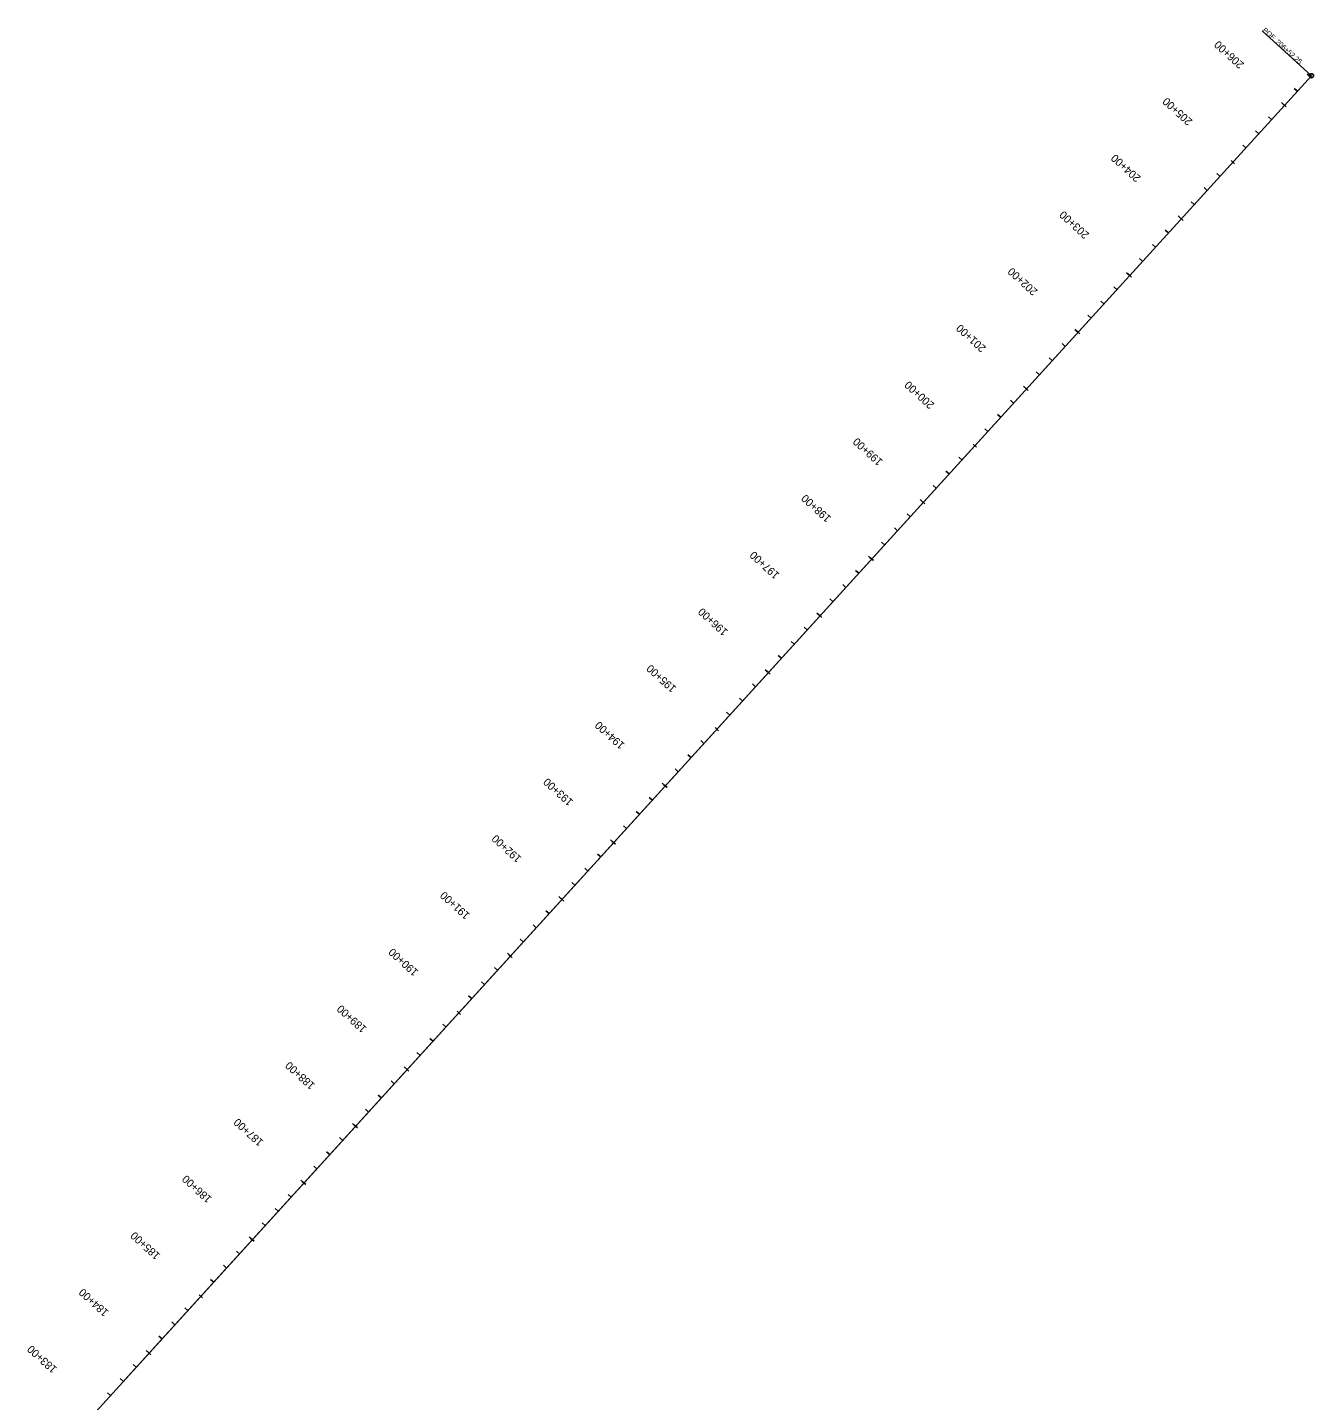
# Model space of a CAD drawing. Extents: x 17535628 to 17537899, y 7333852 to 7342653.
# Drawn here: x 17536222 to 17537899, y 7340862 to 7342653 of the extents above; entities that cross this region are included whole.
import ezdxf

# ---------------------------------------------------------------- set-up
doc = ezdxf.new("R2010")
doc.units = 0
for name, color, linetype in [('Alignment', 7, 'Continuous'), ('Default', 7, 'Continuous'), ('TextAlignment', 7, 'Continuous'), ('TextAlignmentLrg', 7, 'Continuous'), ('TextAlignmentSml', 7, 'Continuous')]:
    doc.layers.add(name, color=color, linetype=linetype)

msp = doc.modelspace()

# ---------------------------------------------------------------- linework, layer by layer
at = {"layer": 'Alignment'}
msp.add_line((17536293.2, 7340828.6), (17537895.9, 7342590.2), dxfattribs=at)
at = {"layer": 'Default'}
msp.add_line((17536348.7, 7340889.5), (17537895.9, 7342590.2), dxfattribs=at)
at = {"layer": 'TextAlignment'}
msp.add_line((17537895.9, 7342590.2), (17537831.6, 7342648.8), dxfattribs=at)
msp.add_circle((17537895.9, 7342590.2), 2.67, dxfattribs=at)
at = {"layer": 'TextAlignmentLrg'}
for p, q in [((17537860.7, 7342551.6), (17537856.7, 7342555.2)), ((17537791.2, 7342479.7), (17537795.7, 7342475.5)), ((17537726.1, 7342403.6), (17537722.1, 7342407.3)), ((17537658.9, 7342329.7), (17537654.8, 7342333.3)), ((17537591.6, 7342255.7), (17537587.5, 7342259.4)), ((17537524.3, 7342181.7), (17537520.2, 7342185.4)), ((17537454.7, 7342109.8), (17537459.2, 7342105.7)), ((17537389.7, 7342033.8), (17537385.6, 7342037.5)), ((17537322.4, 7341959.8), (17537318.3, 7341963.5)), ((17537255.1, 7341885.9), (17537251, 7341889.5)), ((17537187.8, 7341811.9), (17537183.7, 7341815.6)), ((17537118.2, 7341740), (17537122.8, 7341735.9)), ((17537053.2, 7341663.9), (17537049.2, 7341667.6)), ((17536985.9, 7341590), (17536981.9, 7341593.7)), ((17536918.6, 7341516), (17536914.6, 7341519.7)), ((17536851.3, 7341442), (17536847.3, 7341445.7)), ((17536781.8, 7341370.1), (17536786.3, 7341366)), ((17536716.7, 7341294.1), (17536712.7, 7341297.8)), ((17536649.4, 7341220.1), (17536645.4, 7341223.8)), ((17536582.1, 7341146.2), (17536578.1, 7341149.8)), ((17536514.8, 7341072.2), (17536510.8, 7341075.9)), ((17536445.3, 7341000.3), (17536449.8, 7340996.2)), ((17536380.2, 7340924.3), (17536376.2, 7340927.9))]:
    msp.add_line(p, q, dxfattribs=at)
at = {"layer": 'TextAlignmentSml'}
for p, q in [((17537894.4, 7342588.6), (17537890.3, 7342592.2)), ((17537877.6, 7342570.1), (17537873.5, 7342573.7)), ((17537858.5, 7342553.6), (17537863, 7342549.5)), ((17537843.9, 7342533.1), (17537839.9, 7342536.7)), ((17537827.1, 7342514.6), (17537823.1, 7342518.3)), ((17537810.3, 7342496.1), (17537806.2, 7342499.8)), ((17537791.2, 7342479.7), (17537795.7, 7342475.5)), ((17537776.6, 7342459.1), (17537772.6, 7342462.8)), ((17537759.8, 7342440.6), (17537755.8, 7342444.3)), ((17537743, 7342422.1), (17537738.9, 7342425.8)), ((17537723.9, 7342405.7), (17537728.4, 7342401.6)), ((17537709.3, 7342385.1), (17537705.3, 7342388.8)), ((17537692.5, 7342366.6), (17537688.5, 7342370.3)), ((17537675.7, 7342348.2), (17537671.6, 7342351.8)), ((17537656.6, 7342331.7), (17537661.1, 7342327.6)), ((17537642, 7342311.2), (17537638, 7342314.8)), ((17537625.2, 7342292.7), (17537621.2, 7342296.4)), ((17537608.4, 7342274.2), (17537604.3, 7342277.9)), ((17537589.3, 7342257.8), (17537593.8, 7342253.6)), ((17537574.7, 7342237.2), (17537570.7, 7342240.9)), ((17537557.9, 7342218.7), (17537553.9, 7342222.4)), ((17537541.1, 7342200.2), (17537537, 7342203.9)), ((17537522, 7342183.8), (17537526.5, 7342179.7)), ((17537507.4, 7342163.2), (17537503.4, 7342166.9)), ((17537490.6, 7342144.7), (17537486.6, 7342148.4)), ((17537473.8, 7342126.2), (17537469.8, 7342129.9)), ((17537454.7, 7342109.8), (17537459.2, 7342105.7)), ((17537440.1, 7342089.3), (17537436.1, 7342092.9)), ((17537423.3, 7342070.8), (17537419.3, 7342074.4)), ((17537406.5, 7342052.3), (17537402.5, 7342056)), ((17537372.8, 7342015.3), (17537368.8, 7342019)), ((17537387.4, 7342035.8), (17537391.9, 7342031.7)), ((17537356, 7341996.8), (17537352, 7342000.5)), ((17537339.2, 7341978.3), (17537335.2, 7341982)), ((17537320.1, 7341961.9), (17537324.6, 7341957.8)), ((17537305.6, 7341941.3), (17537301.5, 7341945)), ((17537288.7, 7341922.8), (17537284.7, 7341926.5)), ((17537271.9, 7341904.3), (17537267.9, 7341908)), ((17537252.8, 7341887.9), (17537257.3, 7341883.8)), ((17537238.3, 7341867.4), (17537234.2, 7341871)), ((17537221.4, 7341848.9), (17537217.4, 7341852.5)), ((17537204.6, 7341830.4), (17537200.6, 7341834)), ((17537185.5, 7341813.9), (17537190.1, 7341809.8)), ((17537171, 7341793.4), (17537166.9, 7341797.1)), ((17537154.1, 7341774.9), (17537150.1, 7341778.6)), ((17537137.3, 7341756.4), (17537133.3, 7341760.1)), ((17537118.2, 7341740), (17537122.8, 7341735.9)), ((17537103.7, 7341719.4), (17537099.6, 7341723.1)), ((17537086.8, 7341700.9), (17537082.8, 7341704.6)), ((17537070, 7341682.4), (17537066, 7341686.1)), ((17537050.9, 7341666), (17537055.5, 7341661.9)), ((17537036.4, 7341645.5), (17537032.3, 7341649.1)), ((17537019.5, 7341627), (17537015.5, 7341630.6)), ((17537002.7, 7341608.5), (17536998.7, 7341612.1)), ((17536983.6, 7341592), (17536988.2, 7341587.9)), ((17536969.1, 7341571.5), (17536965, 7341575.2)), ((17536952.3, 7341553), (17536948.2, 7341556.7)), ((17536935.4, 7341534.5), (17536931.4, 7341538.2)), ((17536916.3, 7341518.1), (17536920.9, 7341513.9)), ((17536901.8, 7341497.5), (17536897.7, 7341501.2)), ((17536885, 7341479), (17536880.9, 7341482.7)), ((17536868.1, 7341460.5), (17536864.1, 7341464.2)), ((17536849, 7341444.1), (17536853.6, 7341440)), ((17536834.5, 7341423.5), (17536830.4, 7341427.2)), ((17536817.7, 7341405.1), (17536813.6, 7341408.7)), ((17536800.8, 7341386.6), (17536796.8, 7341390.2)), ((17536781.8, 7341370.1), (17536786.3, 7341366)), ((17536767.2, 7341349.6), (17536763.2, 7341353.3)), ((17536750.4, 7341331.1), (17536746.3, 7341334.8)), ((17536733.5, 7341312.6), (17536729.5, 7341316.3)), ((17536714.5, 7341296.2), (17536719, 7341292)), ((17536699.9, 7341275.6), (17536695.9, 7341279.3)), ((17536683.1, 7341257.1), (17536679, 7341260.8)), ((17536666.2, 7341238.6), (17536662.2, 7341242.3)), ((17536647.2, 7341222.2), (17536651.7, 7341218.1)), ((17536632.6, 7341201.6), (17536628.6, 7341205.3)), ((17536615.8, 7341183.2), (17536611.7, 7341186.8)), ((17536599, 7341164.7), (17536594.9, 7341168.3)), ((17536579.9, 7341148.2), (17536584.4, 7341144.1)), ((17536565.3, 7341127.7), (17536561.3, 7341131.3)), ((17536548.5, 7341109.2), (17536544.4, 7341112.9)), ((17536531.7, 7341090.7), (17536527.6, 7341094.4)), ((17536512.6, 7341074.3), (17536517.1, 7341070.1)), ((17536498, 7341053.7), (17536494, 7341057.4)), ((17536481.2, 7341035.2), (17536477.1, 7341038.9)), ((17536464.4, 7341016.7), (17536460.3, 7341020.4)), ((17536445.3, 7341000.3), (17536449.8, 7340996.2)), ((17536430.7, 7340979.7), (17536426.7, 7340983.4)), ((17536413.9, 7340961.2), (17536409.9, 7340964.9)), ((17536397.1, 7340942.8), (17536393, 7340946.4)), ((17536378, 7340926.3), (17536382.5, 7340922.2)), ((17536363.4, 7340905.8), (17536359.4, 7340909.4)), ((17536346.6, 7340887.3), (17536342.6, 7340891)), ((17536329.8, 7340868.8), (17536325.7, 7340872.5))]:
    msp.add_line(p, q, dxfattribs=at)

# ---------------------------------------------------------------- texts
at = {"layer": 'TextAlignment'}
for s, p in [('POE ', (17537831.6, 7342648.8)), ('206+52.25', (17537848.6, 7342633.4))]:
    msp.add_text(s, height=6.48, rotation=317.7046, dxfattribs=at).set_placement(p)
at = {"layer": 'TextAlignmentLrg'}
for s, p in [('205+00', (17537741.4, 7342531.8)), ('200+00', (17537404.9, 7342162)), ('195+00', (17537068.4, 7341792.2)), ('190+00', (17536732, 7341422.3)), ('185+00', (17536395.5, 7341052.5))]:
    msp.add_text(s, height=10.2, rotation=137.7046, dxfattribs=at).set_placement(p)
at = {"layer": 'TextAlignmentSml'}
for s, p in [('206+00', (17537808.7, 7342605.8)), ('205+00', (17537741.4, 7342531.8)), ('204+00', (17537674.1, 7342457.9)), ('203+00', (17537606.8, 7342383.9)), ('202+00', (17537539.5, 7342309.9)), ('201+00', (17537472.2, 7342236)), ('200+00', (17537404.9, 7342162)), ('199+00', (17537337.6, 7342088)), ('198+00', (17537270.3, 7342014.1)), ('197+00', (17537203, 7341940.1)), ('196+00', (17537135.7, 7341866.1)), ('195+00', (17537068.4, 7341792.2)), ('194+00', (17537001.2, 7341718.2)), ('193+00', (17536933.9, 7341644.2)), ('192+00', (17536866.6, 7341570.3)), ('191+00', (17536799.3, 7341496.3)), ('190+00', (17536732, 7341422.3)), ('189+00', (17536664.7, 7341348.3)), ('188+00', (17536597.4, 7341274.4)), ('187+00', (17536530.1, 7341200.4)), ('186+00', (17536462.8, 7341126.4)), ('185+00', (17536395.5, 7341052.5)), ('184+00', (17536328.2, 7340978.5)), ('183+00', (17536260.9, 7340904.5))]:
    msp.add_text(s, height=10.2, rotation=137.7046, dxfattribs=at).set_placement(p)

doc.saveas('drawing.dxf')
